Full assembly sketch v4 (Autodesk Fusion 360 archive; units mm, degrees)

design "Full assembly sketch" references "150mm_glass_base"
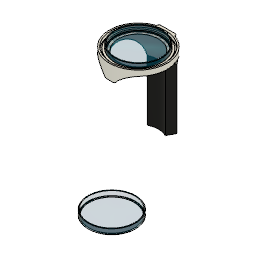
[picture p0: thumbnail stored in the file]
component_insert "Component Insert1"
component_insert "Component Insert2"
position "Position1"
sketch "Sketch1" plane through (0, 400, 0) normal (0, -1, 0) x axis (1, 0, 0)
  circle C1 centre (0, -83.0719) radius 72.5
  circle C2 centre (0, -83.0719) radius 62.9334
  circle C3 centre (0, -83.0719) radius 90.2247
  concentric C1 C2
  concentric C1 C3
extrude "Extrude1" new body sketch "Sketch1" against normal blind 2
sketch "Sketch2" plane through (0, 402, 0) normal (0, 1, 0) x axis (-1, 0, 0)
  circle C1 centre (0, -83.0719) radius 62.9334
  circle C2 centre (0, -83.0719) radius 90.2247
  circle C3 centre (0, -83.0719) radius 74.5
extrude "Extrude2" add sketch "Sketch2" profile of C2 C3 along normal blind 5
sketch "Sketch6" plane through (0, 400, 0) normal (0, -1, 0) x axis (1, 0, 0)
  line L1 (0, 7.1528) -> (0, -83.0719)
  line L2 (-14.9908, 5.8988) -> (-9.3929, -11.1829)
  line L3 (14.9908, 5.8988) -> (9.3929, -11.1829)
  circle C1 centre (0, -83.0719) radius 62.9334
  circle C2 centre (0, -83.0719) radius 90.2247
  circle C3 centre (0, -83.0719) radius 72.5
  point P2 (0, -83.0719)
  point P3 (0, -83.0719)
  point P4 (0, 7.1528)
  point P6 (-9.3929, -11.1829)
  point P7 (-14.9908, 5.8988)
  point P8 (9.3929, -11.1829)
  point P9 (14.9908, 5.8988)
  coincident P2 P3
  coincident C2 P4
  vertical L1
  coincident C3 P6
  coincident C2 P7
  symmetric L1 P6 P8
  symmetric L1 P7 P9
extrude "Extrude3" add sketch "Sketch6" profile of C2 L1 C3 L2 L3 along normal blind 30
work_plane "WorkPlane1" AlongDistance -1
sketch "Sketch7" plane through (0, 406, 0) normal (0, 1, 0) x axis (-1, 0, 0)
  circle C1 centre (0, -83.0719) radius 83.0719
  point P2 (0, -83.0719)
  point P3 (0, -83.0719)
  point P1 (0, 0)
  coincident P2 P3
  coincident P1 C1
pipe "Pipe1" SectionSize 5 SectionThickness 1
extrude "Extrude4" add of existing geometry blind 2
extrude "Extrude5" add of existing geometry blind 1
sketch "Sketch8" plane through (0, 370, 0) normal (0, -1, 0) x axis (1, 0, 0)
  line L1 (2.4997, -2.33) -> (-2.4997, -2.2526)
  line L2 (7.5, -2.4) -> (-7.5, -2.4)
  line L3 (-7.5, 2.4) -> (7.5, 2.4)
  line L4 (7.5, 0) -> (-7.5, 0)
  line L5 (14.9908, 5.8988) -> (9.3929, -11.1829)
  line L6 (-9.3929, -11.1829) -> (-14.9908, 5.8988)
  arc A1 centre (0, -83.0719) radius 72.5 clockwise from (-9.3929, -11.1829) to (9.3929, -11.1829)
  arc A2 centre (0, -83.0719) radius 90.2247 clockwise from (-14.9908, 5.8988) to (14.9908, 5.8988)
  circle C1 centre (0, -83.0719) radius 83.0719
  arc A3 centre (7.5, 0) radius 2.4 clockwise from (7.5, 2.4) to (7.5, -2.4)
  arc A4 centre (-7.5, 0) radius 2.4 clockwise from (-7.5, -2.4) to (-7.5, 2.4)
  point P9 (0, -2.2913)
  point P1 (0, 0)
  point P17 (0, 0)
  point P13 (7.5, 2.4)
  point P14 (-7.5, 2.4)
  midpoint L1 P9
  tangent L2 A3
  tangent A3 L3
  parallel L2 L3
  tangent L3 A4
  tangent L2 A4
  horizontal L4
  coincident P1 P17
  midpoint L4 P17
  dimension "d36" diameter A3 = 4.8
  dimension "d39" distance P13 P14 = 15
extrude "Extrude7" cut sketch "Sketch8" profile of C1 L2 A3 L3 A4 against normal blind 70.827
sketch "Sketch10" plane through (0, 400, 0) normal (0, -1, 0) x axis (1, 0, 0)
  line L1 (-40.5573, -163.6671) -> (0, -83.0719)
  line L2 (0, -173.2965) -> (0, -83.0719)
  line L3 (40.5573, -163.6671) -> (0, -83.0719)
  line L4 (9.3929, -11.1829) -> (14.9908, 5.8988)
  line L5 (-14.9908, 5.8988) -> (-9.3929, -11.1829)
  arc A1 centre (0, -83.0719) radius 90.2247 clockwise from (14.9908, 5.8988) to (-14.9908, 5.8988)
  arc A2 centre (0, -83.0719) radius 72.5 clockwise from (-9.3929, -11.1829) to (9.3929, -11.1829)
  circle C1 centre (0, -83.0719) radius 62.9334
  point P4 (0, -83.0719)
  point P7 (0, -83.0719)
  point P8 (-40.5573, -163.6671)
  point P9 (0, -83.0719)
  point P10 (0, -173.2965)
  point P11 (0, -83.0719)
  point P12 (40.5573, -163.6671)
  coincident P4 P7
  coincident A1 P8
  coincident P4 P9
  midpoint A1 P10
  symmetric P7 L2 P11
  symmetric P8 L2 P12
extrude "Extrude9" add sketch "Sketch10" profile of A1 C1 L1 L2 along normal blind 30
extrude "Extrude10" add sketch "Sketch10" profile of A1 C1 L1 L2 L3 along normal blind 50
fillet "Fillet4" radius 64.581
fillet "Fillet5" radius 80
extrude "Extrude11" add of existing geometry blind 4
extrude "Extrude12" add of existing geometry blind 4
extrude "Extrude13" add of existing geometry blind 4
sketch "Sketch11" plane through (0, 350, 0) normal (0, -1, 0) x axis (1, 0, 0)
  line L1 (28.2895, -139.2886) -> (40.5573, -163.6671)
  line L2 (-40.5573, -163.6671) -> (-28.2895, -139.2886)
  line L3 (0, -180.6965) -> (0, -83.0719)
  line L4 (11.5296, -180.6965) -> (-11.5296, -180.6965)
  circle C1 centre (11.5296, -180.6965) radius 6
  arc A1 centre (0, -83.0719) radius 90.2247 clockwise from (40.5573, -163.6671) to (-40.5573, -163.6671)
  arc A2 centre (0, -83.0719) radius 62.9334 clockwise from (28.2895, -139.2886) to (-28.2895, -139.2886)
  circle C2 centre (-11.5296, -180.6965) radius 6
  point P5 (0, -83.0719)
  point P8 (0, -83.0719)
  point P9 (0, -180.6965)
  point P2 (11.5296, -180.6965)
  point P11 (11.5296, -180.6965)
  point P10 (-11.5296, -180.6965)
  point P12 (-11.5296, -180.6965)
  coincident P5 P8
  vertical L3
  midpoint P9 L4
  horizontal L4
  coincident P2 L4
  coincident P2 P11
  coincident P10 P12
  dimension "d56" diameter C1 = 12
  dimension "d57" diameter C2 = 12
sketch "Sketch12" plane through (0, 350, 0) normal (0, -1, 0) x axis (1, 0, 0)
  line L1 (28.2895, -139.2886) -> (40.5573, -163.6671)
  line L2 (-40.5573, -163.6671) -> (-28.2895, -139.2886)
  line L3 (26.4607, -144.5529) -> (35.1444, -161.8092)
  line L4 (-35.1444, -161.8092) -> (-26.4607, -144.5529)
  arc A1 centre (0, -83.0719) radius 90.2247 clockwise from (40.5573, -163.6671) to (-40.5573, -163.6671)
  arc A2 centre (0, -83.0719) radius 62.9334 clockwise from (28.2895, -139.2886) to (-28.2895, -139.2886)
  arc A3 centre (0, -83.0719) radius 66.9334 clockwise from (26.4607, -144.5529) to (-26.4607, -144.5529)
  arc A4 centre (0, -83.0719) radius 86.2247 clockwise from (35.1444, -161.8092) to (-35.1444, -161.8092)
  dimension "d58" = -4
extrude "Extrude14" cut sketch "Sketch12" profile of L4 L3 A4 A3 against normal blind 40
fillet "Fillet6" radius 4
sketch "Sketch13" plane through (0, 390, 0) normal (0, -1, 0) x axis (1, 0, 0)
  line L1 (28.1091, -147.8286) -> (33.2127, -157.9705)
  line L2 (-33.2127, -157.9705) -> (-28.1091, -147.8286)
  line L3 (27.9751, -147.896) -> (33.0788, -158.038)
  line L4 (-33.0788, -158.038) -> (-27.9751, -147.896)
  arc A1 centre (-29.6397, -159.7686) radius 4 clockwise from (-31.0815, -163.4997) to (-33.2127, -157.9705)
  arc A2 centre (0, -83.0719) radius 86.2247 clockwise from (31.0815, -163.4997) to (-31.0815, -163.4997)
  arc A3 centre (29.6397, -159.7686) radius 4 clockwise from (33.2127, -157.9705) to (31.0815, -163.4997)
  arc A4 centre (24.536, -149.6266) radius 4 clockwise from (23.1524, -145.8736) to (28.1091, -147.8286)
  arc A5 centre (0, -83.0719) radius 66.9334 clockwise from (23.1524, -145.8736) to (-23.1524, -145.8736)
  arc A6 centre (-24.536, -149.6266) radius 4 clockwise from (-28.1091, -147.8286) to (-23.1524, -145.8736)
  arc A7 centre (24.536, -149.6266) radius 3.85 clockwise from (23.2043, -146.0143) to (27.9751, -147.896)
  arc A8 centre (0, -83.0719) radius 67.0834 clockwise from (23.2043, -146.0143) to (-23.2043, -146.0143)
  arc A9 centre (-24.536, -149.6266) radius 3.85 clockwise from (-27.9751, -147.896) to (-23.2043, -146.0143)
  arc A10 centre (-29.6397, -159.7686) radius 3.85 clockwise from (-31.0275, -163.3598) to (-33.0788, -158.038)
  arc A11 centre (0, -83.0719) radius 86.0747 clockwise from (31.0275, -163.3598) to (-31.0275, -163.3598)
  arc A12 centre (29.6397, -159.7686) radius 3.85 clockwise from (33.0788, -158.038) to (31.0275, -163.3598)
  dimension "d63" = -0.15
extrude "Extrude1" new body sketch "Sketch13" profile of A11 L4 A8 A9 A10 A7 A12 L3 along normal blind 40
sketch "Sketch1" plane through (0, 350, 0) normal (0, -1, 0) x axis (1, 0, 0)
  line L1 (-33.0788, -158.038) -> (-27.9751, -147.896)
  line L2 (27.9751, -147.896) -> (33.0788, -158.038)
  line L3 (-28.1091, -147.8286) -> (-33.2127, -157.9705)
  line L4 (33.2127, -157.9705) -> (28.1091, -147.8286)
  line L5 (28.2895, -139.2886) -> (40.5573, -163.6671)
  line L6 (-40.5573, -163.6671) -> (-28.2895, -139.2886)
  arc A1 centre (-24.536, -149.6266) radius 3.85 clockwise from (-27.9751, -147.896) to (-23.2043, -146.0143)
  arc A2 centre (-29.6397, -159.7686) radius 3.85 clockwise from (-31.0275, -163.3598) to (-33.0788, -158.038)
  arc A3 centre (0, -83.0719) radius 86.0747 clockwise from (31.0275, -163.3598) to (-31.0275, -163.3598)
  arc A4 centre (29.6397, -159.7686) radius 3.85 clockwise from (33.0788, -158.038) to (31.0275, -163.3598)
  arc A5 centre (24.536, -149.6266) radius 3.85 clockwise from (23.2043, -146.0143) to (27.9751, -147.896)
  arc A6 centre (0, -83.0719) radius 67.0834 clockwise from (23.2043, -146.0143) to (-23.2043, -146.0143)
  arc A7 centre (0, -83.0719) radius 86.2247 clockwise from (31.0815, -163.4997) to (-31.0815, -163.4997)
  arc A8 centre (-29.6397, -159.7686) radius 4 clockwise from (-31.0815, -163.4997) to (-33.2127, -157.9705)
  arc A9 centre (-24.536, -149.6266) radius 4 clockwise from (-28.1091, -147.8286) to (-23.1524, -145.8736)
  arc A10 centre (0, -83.0719) radius 66.9334 clockwise from (23.1524, -145.8736) to (-23.1524, -145.8736)
  arc A11 centre (24.536, -149.6266) radius 4 clockwise from (23.1524, -145.8736) to (28.1091, -147.8286)
  arc A12 centre (29.6397, -159.7686) radius 4 clockwise from (33.2127, -157.9705) to (31.0815, -163.4997)
  arc A13 centre (0, -83.0719) radius 90.2247 clockwise from (40.5573, -163.6671) to (-40.5573, -163.6671)
  arc A14 centre (0, -83.0719) radius 62.9334 clockwise from (28.2895, -139.2886) to (-28.2895, -139.2886)
extrude "Extrude2" add sketch "Sketch1" along normal blind 188.599 (= "-61.401 mm + 250 mm")
offset_faces "OffsetFaces1" distance -0.2
position "Position2"
extrude "Extrude16" add of existing geometry blind 4
sketch "Sketch1" plane through (0, 417, 0) normal (0, 1, 0) x axis (-1, 0, 0)
  line L1 (63.5281, -193.1058) -> (0, -83.0719)
  line L2 (-63.5281, -193.1058) -> (0, -83.0719)
  line L3 (0, -210.1281) -> (0, -83.0719)
  circle C1 centre (0, -83.0719) radius 90.2247
  circle C2 centre (0, -83.0719) radius 127.0562
  point P2 (0, -83.0719)
  point P4 (0, -83.0719)
  point P5 (63.5281, -193.1058)
  point P6 (0, -83.0719)
  point P7 (-63.5281, -193.1058)
  point P8 (0, -83.0719)
  point P9 (0, -210.1281)
  coincident P2 P4
  coincident C2 P5
  coincident P2 P6
  coincident C2 P7
  coincident P2 P8
  coincident C2 P9
  vertical L3
  dimension "d75" = 36.8315
  dimension "d76" angle L2 L3 = 30
  dimension "d77" angle L1 L3 = 30
work_plane "WorkPlane1" RotateAngle 0
sketch "Sketch2" plane through (0, 0, -173.2965) normal (0, 0, -1) x axis (-1, 0, 0)
  line L1 (-90.2247, 417) -> (90.2247, 417)
  line L2 (14.9908, 370) -> (-14.9908, 370)
  curve K1 (-14.9908, 370) -> (-70.1474, 400)
  line L3 (-70.1474, 400) -> (-90.2247, 400)
  curve K2 (-85.2696, 400) -> (-40.5573, 350)
  line L4 (40.5573, 350) -> (-40.5573, 350)
  curve K3 (40.5573, 350) -> (85.2696, 400)
  line L5 (90.2247, 400) -> (70.1474, 400)
  curve K4 (70.1474, 400) -> (14.9908, 370)
  line L6 (-28.1091, 350) -> (28.1091, 350)
  line L7 (-28.1091, 484) -> (-28.1091, 350)
  line L8 (28.1091, 484) -> (-28.1091, 484)
  line L9 (28.1091, 350) -> (28.1091, 484)
  line L10 (-28.1091, 484) -> (28.1091, 350)
  line L11 (28.1091, 484) -> (-28.1091, 350)
  point P18 (0, 417)
  point P14 (28.1091, 350)
  point P20 (28.1091, 350)
  point P19 (0, 417)
  horizontal L6
  perpendicular L6 L7
  parallel L6 L8
  parallel L7 L9
  coincident L10 P18
  coincident L11 P18
  coincident P14 P20
  coincident P18 P19
extrude "Extrude17" add sketch "Sketch2" profile of L1 L2 K1 L4 K4 L6 L7 L9 along normal blind 2.555 and against normal blind 5.05
fillet "Fillet7" radius 4
sketch "Sketch3" plane through (0, 0, -175.8515) normal (0, 0, -1) x axis (-1, 0, 0)
  line L1 (-24.1091, 350) -> (-24.1091, 417)
  line L2 (24.1091, 350) -> (-24.1091, 350)
  line L3 (24.1091, 417) -> (24.1091, 350)
  line L4 (-24.1091, 417) -> (24.1091, 417)
  line L5 (-17.3784, 358.8391) -> (17.3784, 358.8391)
  line L6 (-17.3784, 406.8391) -> (-17.3784, 358.8391)
  line L7 (17.3784, 406.8391) -> (-17.3784, 406.8391)
  line L8 (17.3784, 358.8391) -> (17.3784, 406.8391)
  line L9 (-17.3784, 406.8391) -> (17.3784, 358.8391)
  line L10 (17.3784, 406.8391) -> (-17.3784, 358.8391)
  line L11 (17.3784, 382.8391) -> (-17.3784, 382.8391)
  point P10 (0, 382.8391)
  point P11 (-17.3784, 382.8391)
  point P12 (17.3784, 382.8391)
  point P7 (-17.3784, 358.8391)
  point P8 (-17.3784, 406.8391)
  horizontal L5
  perpendicular L5 L6
  parallel L5 L7
  parallel L6 L8
  coincident L9 P10
  coincident L10 P10
  midpoint L6 P11
  midpoint L8 P12
  dimension "d85" distance P7 P8 = 48
hole "Hole1" HoleDepth 9 HoleDiameter 4 TipAngle 180
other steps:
hole "Hole1" HoleDepth 9 HoleDiameter 4 TipAngle 180
create_component "CreateComponent1"
create_component "CreateComponent2"

design "150mm_glass_base"
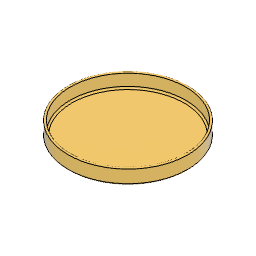
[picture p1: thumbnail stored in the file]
sketch "Sketch1" plane through (0, 0, 0) normal (0, 1, 0) x axis (1, 0, 0)
  circle C1 centre (0, 0) radius 71.15
  circle C2 centre (0, 0) radius 74.5
  point P1 (0, 0)
  point P2 (0, 0)
  coincident P1 P2
  dimension "d2" = 3.35
  dimension "d14" diameter C2 = 149
extrude "Extrude1" new body sketch "Sketch1" along normal blind 1.56 bodies "Base"
sketch "Sketch2" plane through (0, 1.56, 0) normal (0, 1, 0) x axis (-1, 0, 0)
  circle C1 centre (0, 0) radius 74.5
  circle C2 centre (0, 0) radius 72
  dimension "d5" = -2.5
extrude "Extrude2" add sketch "Sketch2" along normal blind 17.5
fillet "Fillet1" radius 2 1.25
fillet "Fillet2" radius 2
named bodies: "Base"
